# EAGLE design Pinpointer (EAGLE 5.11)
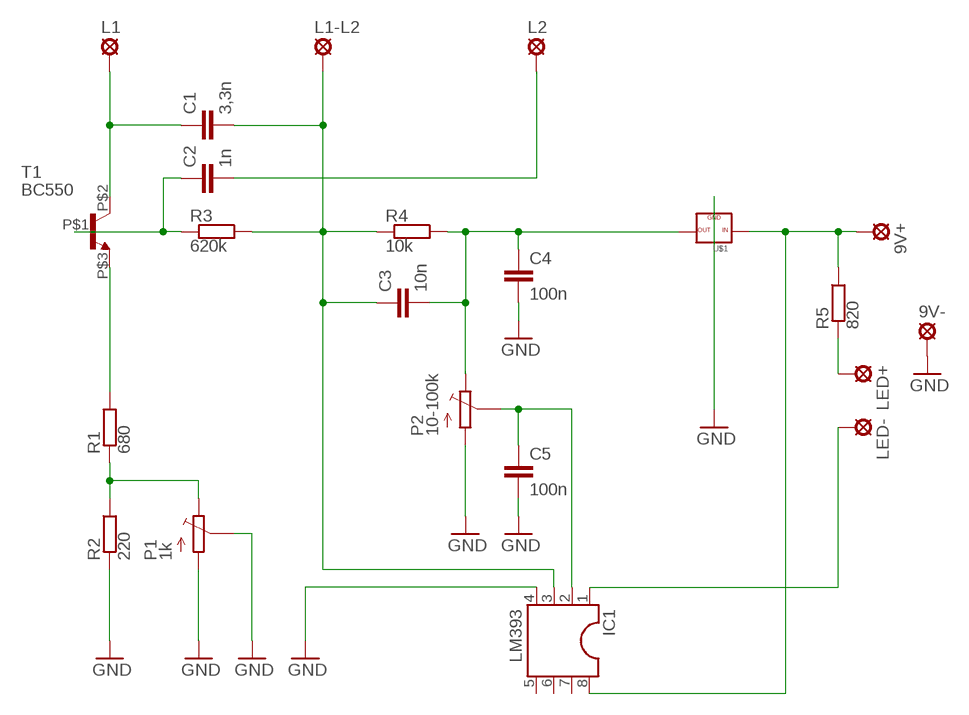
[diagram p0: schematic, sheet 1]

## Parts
9V+  9V  LSP11  [LSP11]
9V-  GND  LSP11  [LSP11]
C1  3,3n  CAPACITOR  [CAPACITOR]
C2  1n  CAPACITOR  [CAPACITOR]
C3  10n  CAPACITOR  [CAPACITOR]
C4  100n  CAPACITOR  [CAPACITOR]
C5  100n  CAPACITOR  [CAPACITOR]
IC1  LM393  DIL8  [DIL08]
L1  LSP11  [LSP11]
L1-L2  LSP11  [LSP11]
L2  LSP11  [LSP11]
LED+  LSP11  [LSP11]
LED-  LSP11  [LSP11]
P1  1k  TRIMMER  [POTI_PAD]
P2  10-100k  TRIMMERKOZEPES  [KÖZEPES]
R1  680  RESISTOR  [RESISTOR]
R2  220  RESISTOR  [RESISTOR]
R3  620k  RESISTOR  [RESISTOR]
R4  10k  RESISTOR  [RESISTOR]
R5  820  RESISTOR  [RESISTOR]
T1  BC550  BC_2  [BC_2]
U$1  LM78L05  LM78XX  [78XX]

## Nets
GND: 9V-.MP C4.P$2 C5.P$2 IC1.4 P1.P$1(A) P1.P$3(S) P2.P$3(A) R2.P$2 U$1.P$2
N$1: P1.P$2(E) R1.P$2 R2.P$1
N$2: C1.P$1 L1.MP T1.P$2(C)
N$3: C1.P$2 C3.P$1 IC1.3 L1-L2.MP R3.P$1 R4.P$2
N$4: LED+.MP R5.P$2
N$5: C3.P$2 C4.P$1 P2.P$2(E) R4.P$1 U$1.P$3
N$6: IC1.1 LED-.MP
N$7: C5.P$1 IC1.2 P2.P$1(S)
N$8: C2.P$2 L2.MP
N$9: R1.P$1 T1.P$3(E)
N$10: 9V+.MP IC1.8 R5.P$1 U$1.P$1
N$11: C2.P$1 R3.P$2 T1.P$1(B)
Unconnected: IC1.5 IC1.6 IC1.7

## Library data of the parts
9V+ 9V- L1 L1-L2 L2 LED+ LED- = solpad:LSP11: SOLDER PAD
C1-C5 = x_capacitor:CAPACITOR
IC1 = ic-package:DIL8: Dual In Line / Socket
P1 P2 = x_poti:TRIMMER
R1-R5 = x_resistor:RESISTOR
T1 = x_transistor:BC_2
U$1 = x_regulator:LM78XX

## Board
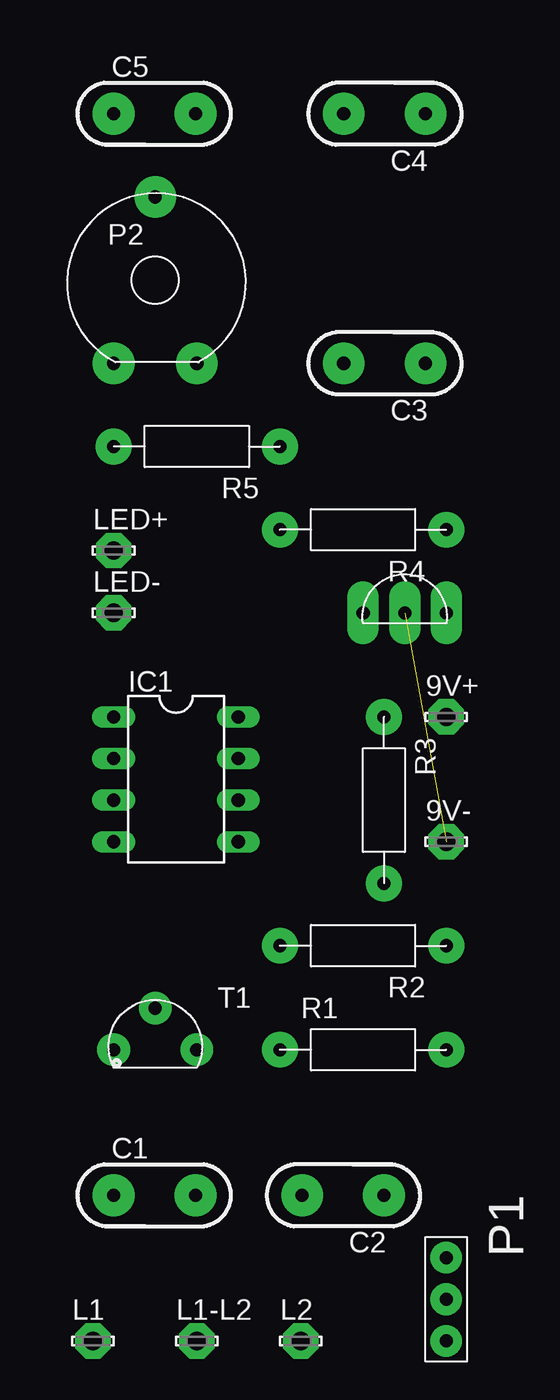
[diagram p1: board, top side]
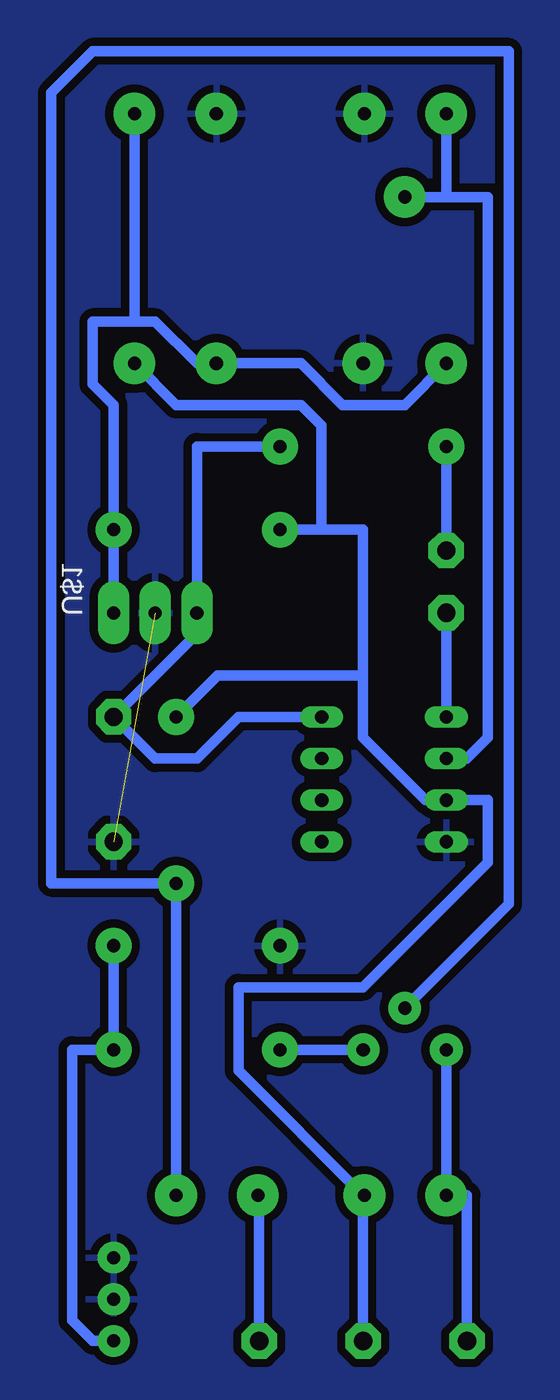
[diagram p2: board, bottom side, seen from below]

No outline drawn. Coordinates in mm, seen from the top.
Copper layers (1*16): Top 0.035mm / dielectric 1.5mm / Bottom 0.035mm
Design rules "default *": minimum track width 25mil, minimum drill 30mil, track to track 20mil, track to pad 20mil, pad to pad 8mil, via to via 8mil, smd to smd 8mil, copper to edge 40mil, drill to drill 8mil, minimum pad ring 10mil, minimum via ring 8mil, stop-mask expansion 4mil, vias tented up to drill 0mil, thermal gap 20mil

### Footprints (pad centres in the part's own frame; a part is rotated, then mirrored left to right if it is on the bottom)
LSP11 = drill 1.118 pad 2.159 octagon: MP 0,0
CAPACITOR = drill 0.8 pad 2.54 round: P$1 -2.54,0; P$2 2.46,0
DIL08 = drill 0.813 long: 1 -3.81,-3.81; 2 -1.27,-3.81; 3 1.27,-3.81; 4 3.81,-3.81; 5 3.81,3.81; 6 1.27,3.81; 7 -1.27,3.81; 8 -3.81,3.81
POTI_PAD = drill 0.8 pad 1.93 round: P$1 -2.54,0; P$2 2.54,0; P$3 0,0
KÖZEPES = drill 0.8 pad 2.54 round: P$1 0,5.08; P$2 -2.54,-5.08; P$3 2.54,-5.08
RESISTOR = drill 0.8 pad 2.184 round: P$1 -5.08,0; P$2 5.08,0
BC_2 = drill 0.8 pad 2 round: P$1 0,2.54; P$2 -2.54,0; P$3 2.54,0
78XX = drill 0.8 pad 1.93 long: P$1 0,-2.54; P$2 0,0; P$3 0,2.54

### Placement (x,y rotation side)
9V+  31.75,25.4 0 top
9V-  31.75,17.78 0 top
C1  13.97,-3.81 0 top
C2  25.4,-3.81 180 top
C3  27.94,46.99 180 top
C4  27.94,62.23 180 top
C5  13.97,62.23 0 top
IC1  15.24,21.59 270 top
L1  10.16,-12.7 0 top
L1-L2  16.51,-12.7 0 top
L2  22.86,-12.7 0 top
LED+  11.43,35.56 0 top
LED-  11.43,31.75 0 top
P1  31.75,-10.16 270 top
P2  13.97,52.07 0 top
R1  26.67,5.08 0 top
R2  26.67,11.43 180 top
R3  27.94,20.32 270 top
R4  26.67,36.83 180 top
R5  16.51,41.91 180 top
T1  13.97,5.08 0 top
U$1  29.21,31.75 270 top

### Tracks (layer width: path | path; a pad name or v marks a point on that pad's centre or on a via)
GND  (1 unrouted)
  pour Bottom: 2.54,69.85 39.37,69.85 39.37,-16.51 2.54,-16.51
N$1
  Bottom 0.635: P1.P$2 33.02,-12.7 34.29,-11.43 34.29,5.08 R1.P$2 R2.P$1
N$2
  Bottom 0.635: T1.P$2 C1.P$1 10.16,-3.81 L1.MP
N$3
  Bottom 0.635: L1-L2.MP 16.51,-3.81 | 16.51,27.94 16.51,36.83 19.05,36.83 | 16.51,27.94 16.51,24.13 12.7,20.32 IC1.3 8.89,20.32 8.89,16.51 16.51,8.89 24.13,8.89 24.13,3.81 16.51,-3.81 | 19.05,36.83 R4.P$2 | R3.P$1 25.4,27.94 16.51,27.94 | C3.P$1 27.94,44.45 20.32,44.45 19.05,43.18 19.05,36.83 | 16.51,-3.81 C1.P$2
N$4
  Bottom 0.635: LED+.MP R5.P$2
N$5
  Bottom 0.635: U$1.P$3 R4.P$1 31.75,44.45 33.02,45.72 33.02,49.53 30.48,49.53 | P2.P$2 13.97,44.45 17.78,44.45 20.32,46.99 C3.P$2 26.67,46.99 29.21,49.53 30.48,49.53 | 30.48,49.53 C4.P$1
N$6
  Bottom 0.635: IC1.1 LED-.MP
N$7
  Bottom 0.635: IC1.2 10.16,22.86 8.89,24.13 8.89,57.15 11.43,57.15 | 11.43,57.15 P2.P$1 | 11.43,57.15 C5.P$1
N$8
  Bottom 0.635: L2.MP 22.86,-3.81 C2.P$2
N$9
  Bottom 0.635: T1.P$3 R1.P$1
N$10
  Bottom 0.635: IC1.8 24.13,25.4 26.67,22.86 29.21,22.86 9V+.MP 26.67,30.48 U$1.P$1 26.67,41.91 R5.P$1
N$11
  Bottom 0.635: T1.P$1 7.62,13.97 7.62,66.04 33.02,66.04 35.56,63.5 35.56,15.24 R3.P$2 C2.P$1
